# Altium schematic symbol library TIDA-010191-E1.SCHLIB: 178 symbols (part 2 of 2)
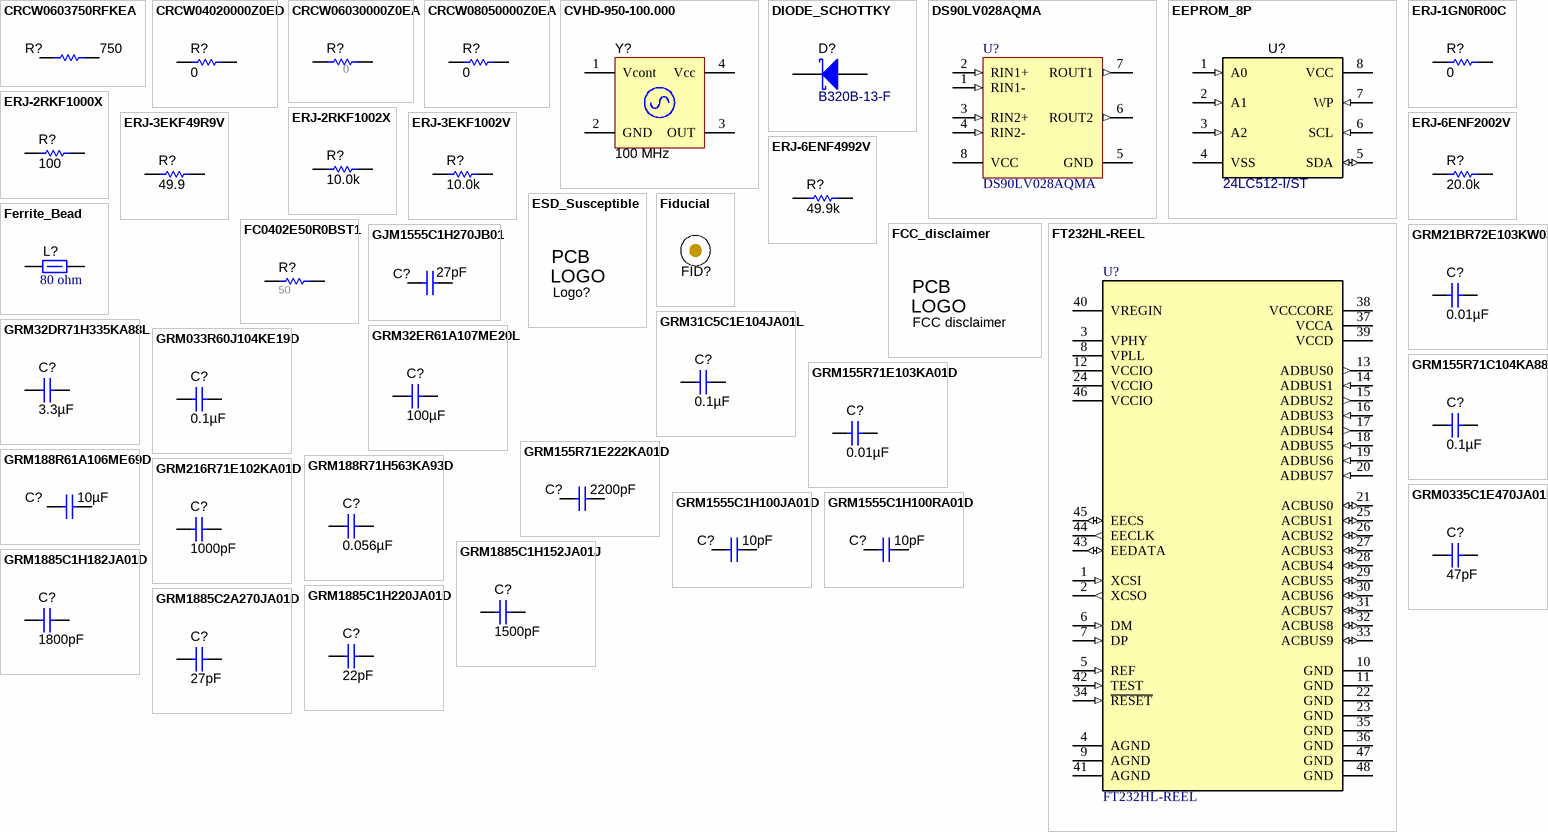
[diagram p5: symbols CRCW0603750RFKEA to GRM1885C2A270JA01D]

## GRM31C5C1E104JA01L
designator C?  ValueDisplayed: 0.1µF  (hidden comment: GRM31C5C1E104JA01L)
CAP, CERM, 0.1 µF, 25 V,+/- 5%, C0G/NP0, 1206; Manufacturer: MuRata; Polarized: N; CompType: Capacitor; Value: 0.1uF; U/M: EA; Cap_F: 0.0000001; Tolerance_%: 5; VDC_V: 25; Value2: 25V; TaMin_C: -55; TaMax_C: 125; Cap_Case: 1206; SizeArea_mm2: 5.12; SizeAreaWB_mm2: 10.92; SizeX_mm: 3.2; SizeY_mm: 1.6; SizeZ_mm: 1.8; AEC Category: Q200
signal-integrity model Cap
simulation model Cap
footprint 1206_180
footprint 1206_180M
footprint 1206_180L
pins: 1, 2

## GRM32DR71H335KA88L
designator C?  ValueDisplayed: 3.3µF  (hidden comment: GRM32DR71H335KA88L)
CAP, CERM, 3.3 µF, 50 V,+/- 10%, X7R, 1210; Manufacturer: MuRata; Polarized: N; CompType: Capacitor; Value: 3.3uF; U/M: EA; Cap_F: 0.0000033; Tolerance_%: 10; ESR_ohm: 0.003; Value1: 0.003 ohm; VDC_V: 50; Value2: 50V; TaMin_C: -55; TaMax_C: 125; Cap_Case: 1210; SizeArea_mm2: 8; SizeAreaWB_mm2: 14.7; SizeX_mm: 3.2; SizeY_mm: 2.5; SizeZ_mm: 2.2; AEC Category: Q200; Green_Lifecycle: Active; Green_REACh: Passed
signal-integrity model Cap
simulation model Cap
footprint 1210_220
footprint 1210_220M
footprint 1210_220L
pins: 1, 2

## GRM32ER61A107ME20L
designator C?  ValueDisplayed: 100µF  (hidden comment: GRM32ER61A107ME20L)
CAP, CERM, 100 µF, 10 V, +/- 20%, X5R, 1210; Manufacturer: MuRata; Polarized: N; CompType: Capacitor; Value: 100uF; U/M: EA; Cap_F: 0.0001; Tolerance_%: 20; Value1: Unknown; VDC_V: 10; Value2: 10V; TaMin_C: -55; TaMax_C: 85; Cap_Case: 1210; SizeArea_mm2: 8; SizeAreaWB_mm2: 14.7; SizeX_mm: 3.2; SizeY_mm: 2.5; SizeZ_mm: 2.7; AEC Category: Q200
signal-integrity model Cap
simulation model Cap
footprint 1210_270
footprint 1210_270M
footprint 1210_270L
pins: 1, 2

## GRM033R60J104KE19D
designator C?  ValueDisplayed: 0.1µF  (hidden comment: GRM033R60J104KE19D)
CAP, CERM, 0.1 µF, 6.3 V, +/- 10%, X5R, 0201; Manufacturer: MuRata; Polarized: N; CompType: Capacitor; Value: 0.1uF; U/M: EA; Cap_F: 0.0000001; Tolerance_%: 10; Value1: Unknown; VDC_V: 6.3; Value2: 6.3V; TaMin_C: -55; TaMax_C: 85; Cap_Case: 0201; SizeArea_mm2: 0.18; SizeAreaWB_mm2: 2.08; SizeX_mm: 0.6; SizeY_mm: 0.3; SizeZ_mm: 0.33; AEC Category: Q200
signal-integrity model Cap
simulation model Cap
footprint 0201_033
footprint 0201_033M
footprint 0201_033L
pins: 1, 2

## GRM155R71C104KA88D
designator C?  ValueDisplayed: 0.1µF  (hidden comment: GRM155R71C104KA88D)
CAP, CERM, 0.1 µF, 16 V, +/- 10%, X7R, 0402; Manufacturer: MuRata; Polarized: N; CompType: Capacitor; Value: 0.1uF; U/M: EA; Cap_F: 0.0000001; Tolerance_%: 10; Value1: Unknown; VDC_V: 16; Value2: 16V; TaMin_C: -55; TaMax_C: 125; Cap_Case: 0402; SizeArea_mm2: 0.5; SizeAreaWB_mm2: 3; SizeX_mm: 1; SizeZ_mm: 0.6; AEC Category: Q200
signal-integrity model Cap
simulation model Cap
footprint 0402
footprint 0402M
footprint 0402L
footprint 0402S
pins: 1, 2

## GRM155R71E103KA01D
designator C?  ValueDisplayed: 0.01µF  (hidden comment: GRM155R71E103KA01D)
CAP, CERM, 0.01 µF, 25 V, +/- 10%, X7R, 0402; Manufacturer: MuRata; Polarized: N; CompType: Capacitor; Value: 0.01uF; U/M: EA; Cap_F: 0.00000001; Tolerance_%: 10; Value1: Unknown; VDC_V: 25; Value2: 25V; TaMin_C: -55; TaMax_C: 125; Cap_Case: 0402; SizeArea_mm2: 0.5; SizeAreaWB_mm2: 3; SizeX_mm: 1; SizeZ_mm: 0.6; AEC Category: Q200
signal-integrity model Cap
simulation model Cap
footprint 0402
footprint 0402M
footprint 0402L
footprint 0402S
pins: 1, 2

## GRM155R71E222KA01D
designator C?  ValueDisplayed: 2200pF  (hidden comment: GRM155R71E222KA01D)
CAP, CERM, 2200 pF, 25 V, +/- 10%, X7R, 0402; Manufacturer: MuRata; Polarized: N; CompType: Capacitor; Value: 2200pF; U/M: EA; Cap_F: 0.0000000022; Tolerance_%: 10; Value1: Unknown; VDC_V: 25; Value2: 25V; TaMin_C: -55; TaMax_C: 125; Cap_Case: 0402; SizeArea_mm2: 0.5; SizeAreaWB_mm2: 3; SizeX_mm: 1; SizeZ_mm: 0.6; AEC Category: Q200
signal-integrity model Cap
simulation model Cap
footprint 0402
footprint 0402M
footprint 0402L
footprint 0402S
pins: 1, 2

## GRM188R61A106ME69D
designator C?  ValueDisplayed: 10µF  (hidden comment: GRM188R61A106ME69D)
CAP, CERM, 10 µF, 10 V, +/- 20%, X5R, 0603; Manufacturer: MuRata; Polarized: N; CompType: Capacitor; Value: 10uF; U/M: EA; Cap_F: 0.00001; Tolerance_%: 20; Value1: Unknown; VDC_V: 10; Value2: 10V; TaMin_C: -55; TaMax_C: 85; Cap_Case: 0603; SizeArea_mm2: 1.28; SizeAreaWB_mm2: 4.68; SizeX_mm: 1.6; SizeY_mm: 0.8; SizeZ_mm: 1; AEC Category: Q200
signal-integrity model Cap
simulation model Cap
footprint 0603
footprint 0603M
footprint 0603L
footprint 0603_HV
footprint 0603S
pins: 1, 2

## GRM188R71H563KA93D
designator C?  ValueDisplayed: 0.056µF  (hidden comment: GRM188R71H563KA93D)
CAP, CERM, 0.056 µF, 50 V,+/- 10%, X7R, 0603; Manufacturer: MuRata; Cap_Case: 0603; Polarized: N; TaMax_C: 125; TaMin_C: -55; Tolerance_%: 10; VDC_V: 50; Cap_F: 0.000000056; CompType: Capacitor; Value: 0.056uF; Value2: 50V; U/M: EA; AEC Category: Q200; SizeArea_mm2: 1.28; SizeAreaWB_mm2: 4.68; SizeX_mm: 1.6; SizeY_mm: 0.8; SizeZ_mm: 1; Green_Lifecycle: Active; Green_REACh: Passed
signal-integrity model Cap
simulation model Cap
footprint 0603
footprint 0603M
footprint 0603L
footprint 0603_HV
footprint 0603S
pins: 1, 2

## GRM216R71E102KA01D
designator C?  ValueDisplayed: 1000pF  (hidden comment: GRM216R71E102KA01D)
CAP, CERM, 1000 pF, 25 V,+/- 10%, X7R, 0805; Manufacturer: MuRata; Polarized: N; CompType: Capacitor; Value: 1000pF; U/M: EA; Cap_F: 0.000000001; Tolerance_%: 10; VDC_V: 25; Value2: 25V; TaMin_C: -55; TaMax_C: 125; Cap_Case: 0805; SizeArea_mm2: 2.5; SizeAreaWB_mm2: 6.75; SizeX_mm: 2; SizeY_mm: 1.25; SizeZ_mm: 1.45; AEC Category: Q200; Green_Lifecycle: Active; Green_REACh: Passed
signal-integrity model Cap
simulation model Cap
footprint 0805_HV
footprint 0805_HV1
footprint 0805
footprint 0805M
footprint 0805L
pins: 1, 2

## GRM0335C1E470JA01D
designator C?  ValueDisplayed: 47pF  (hidden comment: GRM0335C1E470JA01D)
CAP, CERM, 47 pF, 25 V, +/- 5%, C0G/NP0, 0201; Manufacturer: MuRata; Polarized: N; CompType: Capacitor; Value: 47pF; U/M: EA; Cap_F: 0.000000000047; Tolerance_%: 5; Value1: Unknown; VDC_V: 25; Value2: 25V; TaMin_C: -55; TaMax_C: 125; Cap_Case: 0201; SizeArea_mm2: 0.18; SizeAreaWB_mm2: 2.08; SizeX_mm: 0.6; SizeY_mm: 0.3; SizeZ_mm: 0.33; AEC Category: Q200
signal-integrity model Cap
simulation model Cap
footprint 0201_033
footprint 0201_033M
footprint 0201_033L
pins: 1, 2

## GRM1555C1H100JA01D
designator C?  ValueDisplayed: 10pF  (hidden comment: GRM1555C1H100JA01D)
CAP, CERM, 10 pF, 50 V, +/- 5%, C0G/NP0, 0402; Manufacturer: MuRata; Polarized: N; CompType: Capacitor; Value: 10pF; U/M: EA; Cap_F: 0.00000000001; Tolerance_%: 5; Value1: Unknown; VDC_V: 50; Value2: 50V; TaMin_C: -55; TaMax_C: 125; Cap_Case: 0402; SizeArea_mm2: 0.5; SizeAreaWB_mm2: 3; SizeX_mm: 1; SizeZ_mm: 0.6; AEC Category: Q200
signal-integrity model Cap
simulation model Cap
footprint 0402
footprint 0402M
footprint 0402L
footprint 0402S
pins: 1, 2

## GRM1555C1H100RA01D
designator C?  ValueDisplayed: 10pF  (hidden comment: GRM1555C1H100RA01D)
CAP, CERM, 10 pF, 50 V,+/- 4%, C0G/NP0, 0402; Manufacturer: MuRata; Polarized: N; CompType: Capacitor; Value: 10pF; U/M: EA; Cap_F: 0.00000000001; Tolerance_%: 4; VDC_V: 50; Value2: 50V; TaMin_C: -55; TaMax_C: 125; Cap_Case: 0402; SizeArea_mm2: 0.5; SizeAreaWB_mm2: 3; SizeX_mm: 1; SizeZ_mm: 0.6; AEC Category: Q200
signal-integrity model Cap
simulation model Cap
footprint 0402
footprint 0402M
footprint 0402L
footprint 0402S
pins: 1, 2

## GRM1885C1H152JA01J
designator C?  ValueDisplayed: 1500pF  (hidden comment: GRM1885C1H152JA01J)
CAP, CERM, 1500 pF, 50 V,+/- 5%, C0G/NP0, 0603; Manufacturer: MuRata; Cap_Case: 0603; Polarized: N; TaMax_C: 125; TaMin_C: -55; Tolerance_%: 5; VDC_V: 50; Cap_F: 0.0000000015; CompType: Capacitor; Value: 1500pF; Value2: 50V; U/M: EA; AEC Category: Q200; SizeArea_mm2: 1.28; SizeAreaWB_mm2: 4.68; SizeX_mm: 1.6; SizeY_mm: 0.8; SizeZ_mm: 1
signal-integrity model Cap
simulation model Cap
footprint 0603
footprint 0603M
footprint 0603L
footprint 0603_HV
footprint 0603S
pins: 1, 2

## GRM1885C1H182JA01D
designator C?  ValueDisplayed: 1800pF  (hidden comment: GRM1885C1H182JA01D)
CAP, CERM, 1800 pF, 50 V,+/- 5%, C0G/NP0, 0603; Manufacturer: MuRata; Cap_Case: 0603; Polarized: N; TaMax_C: 125; TaMin_C: -55; Tolerance_%: 5; VDC_V: 50; Cap_F: 0.0000000018; CompType: Capacitor; Value: 1800pF; Value2: 50V; U/M: EA; SizeArea_mm2: 1.28; SizeAreaWB_mm2: 4.68; SizeX_mm: 1.6; SizeY_mm: 0.8; SizeZ_mm: 1; AEC Category: Q200
signal-integrity model Cap
simulation model Cap
footprint 0603
footprint 0603M
footprint 0603L
footprint 0603_HV
footprint 0603S
pins: 1, 2

## GRM1885C1H220JA01D
designator C?  ValueDisplayed: 22pF  (hidden comment: GRM1885C1H220JA01D)
CAP, CERM, 22 pF, 50 V,+/- 5%, C0G/NP0, 0603; Manufacturer: MuRata; Polarized: N; CompType: Capacitor; Value: 22pF; U/M: EA; Cap_F: 0.000000000022; Tolerance_%: 5; VDC_V: 50; Value2: 50V; TaMin_C: -55; TaMax_C: 125; Cap_Case: 0603; SizeArea_mm2: 1.28; SizeAreaWB_mm2: 4.68; SizeX_mm: 1.6; SizeY_mm: 0.8; SizeZ_mm: 1; AEC Category: Q200; Green_Lifecycle: Active; Green_REACh: Passed
signal-integrity model Cap
simulation model Cap
footprint 0603
footprint 0603M
footprint 0603L
footprint 0603_HV
footprint 0603S
pins: 1, 2

## GRM1885C2A270JA01D
designator C?  ValueDisplayed: 27pF  (hidden comment: GRM1885C2A270JA01D)
CAP, CERM, 27 pF, 100 V, +/- 5%, C0G/NP0, 0603; Manufacturer: MuRata; Polarized: N; CompType: Capacitor; Value: 27pF; U/M: EA; Cap_F: 0.000000000027; Tolerance_%: 5; Value1: Unknown; VDC_V: 100; Value2: 100V; TaMin_C: -55; TaMax_C: 125; Cap_Case: 0603; SizeArea_mm2: 1.28; SizeAreaWB_mm2: 4.68; SizeX_mm: 1.6; SizeY_mm: 0.8; SizeZ_mm: 1; AEC Category: Q200
signal-integrity model Cap
simulation model Cap
footprint 0603
footprint 0603M
footprint 0603L
footprint 0603_HV
footprint 0603S
pins: 1, 2

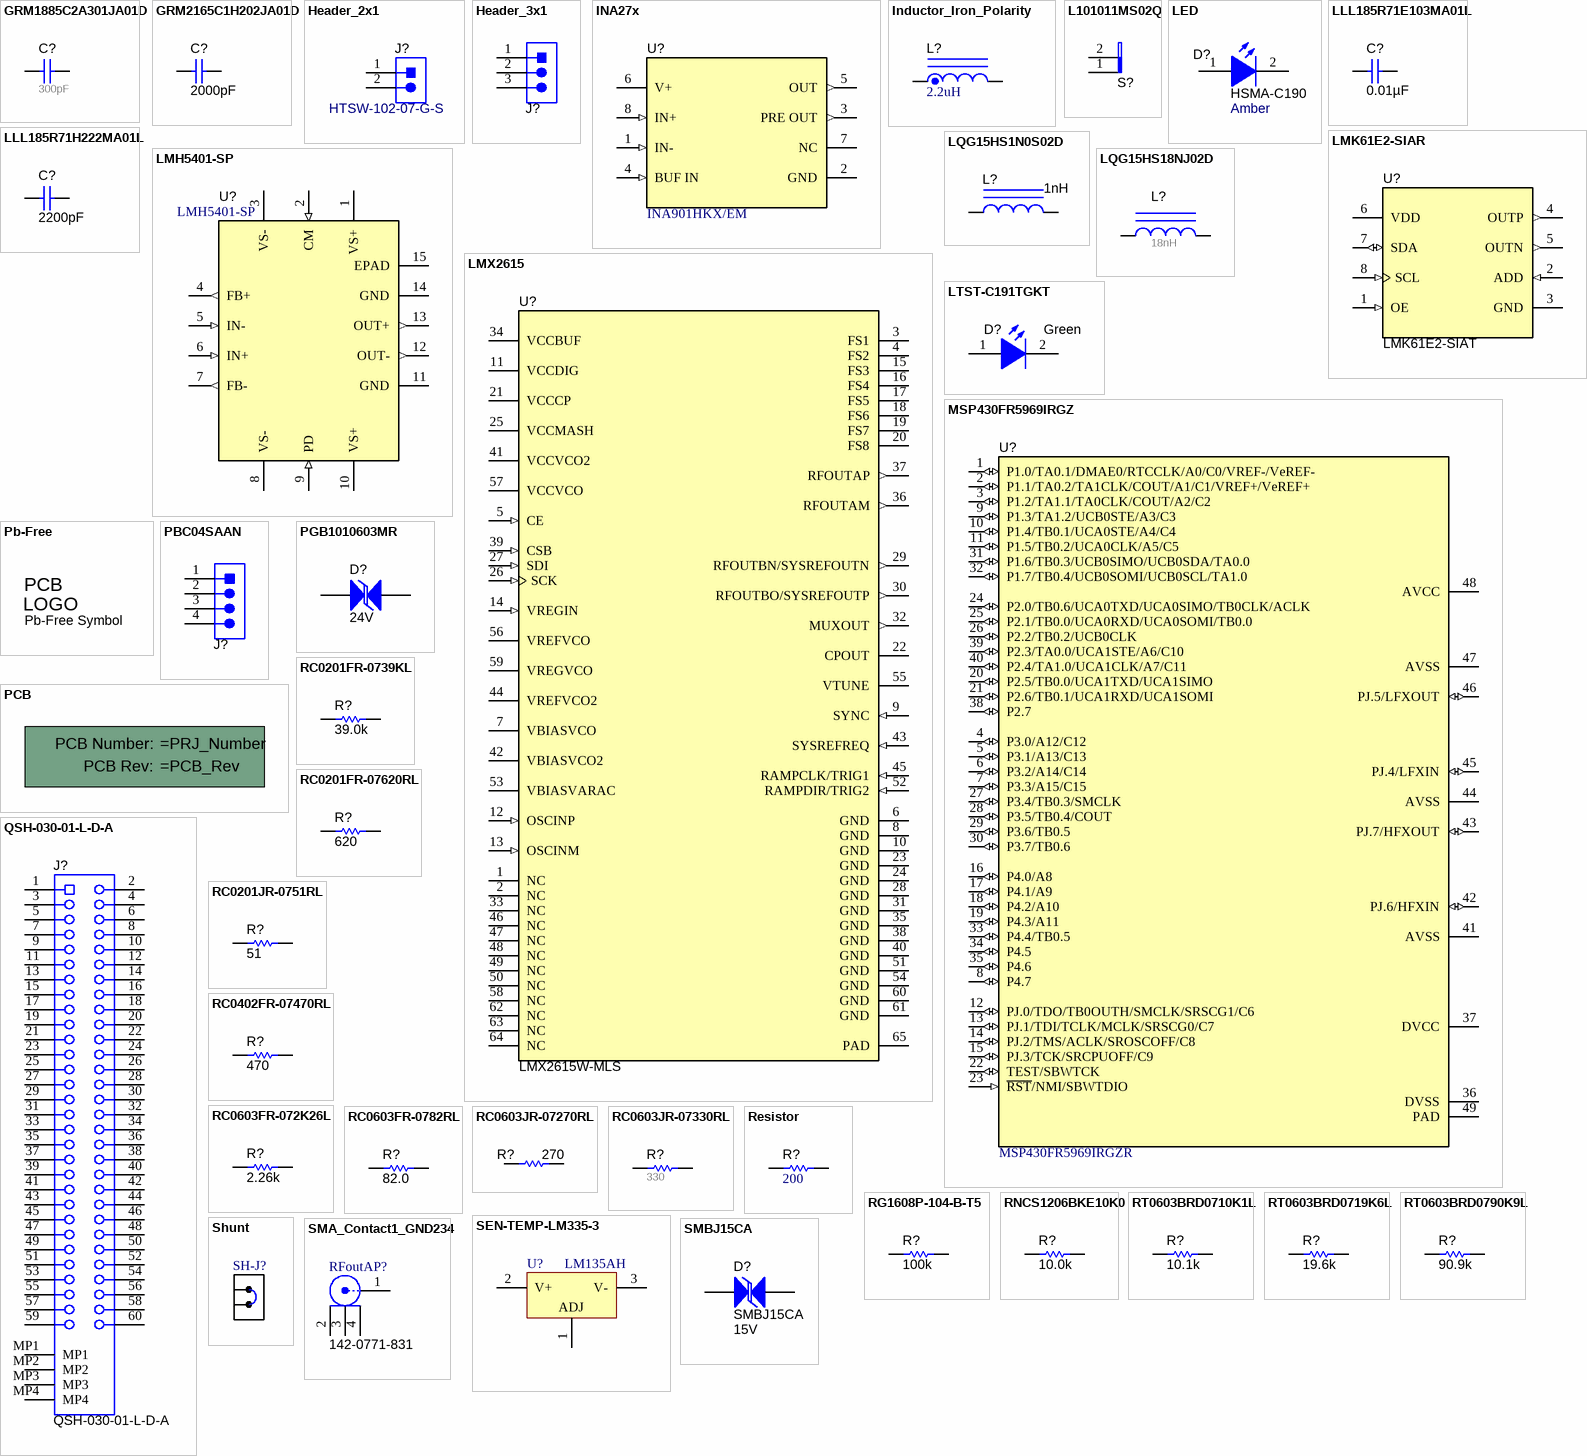
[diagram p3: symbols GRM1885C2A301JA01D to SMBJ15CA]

## GRM1885C2A301JA01D
designator C?  ValueDisplayed: 300pF  (hidden comment: GRM1885C2A301JA01D)
CAP, CERM, 300pF, 100V, +/-5%, C0G/NP0, 0603; Manufacturer: MuRata; Cap_Case: 0603; Polarized: N; TaMax_C: 125; TaMin_C: -55; Tolerance_%: 5; VDC_V: 100; Cap_F: 0.0000000003; CompType: Capacitor; Value1: Unknown; U/M: EA
signal-integrity model Cap
simulation model Cap
footprint 0603
footprint 0603M
footprint 0603L
footprint 0603_HV
footprint 0603S
pins: 1, 2

## GRM2165C1H202JA01D
designator C?  ValueDisplayed: 2000pF  (hidden comment: GRM2165C1H202JA01D)
CAP, CERM, 2000 pF, 50 V,+/- 5%, C0G/NP0, 0805; Manufacturer: MuRata; Polarized: N; CompType: Capacitor; Value: 2000pF; U/M: EA; Cap_F: 0.000000002; Tolerance_%: 5; VDC_V: 50; Value2: 50V; TaMin_C: -55; TaMax_C: 125; Cap_Case: 0805; SizeArea_mm2: 2.5; SizeAreaWB_mm2: 6.75; SizeX_mm: 2; SizeY_mm: 1.25; SizeZ_mm: 1.45; AEC Category: Q200
signal-integrity model Cap
simulation model Cap
footprint 0805_HV
footprint 0805_HV1
footprint 0805
footprint 0805M
footprint 0805L
pins: 1, 2

## Header_2x1
designator J?, comment HTSW-102-07-G-S
Header, 100mil, 2x1, Gold, TH; Manufacturer: Samtec; Green_REACh: Passed; CT: False; Green_Lifecycle: Active; CNHeader: True
footprint Samtec_HTSW-102-07-G-S (Samtec 100mil, 1x2, 230 mil above insulator)
pins: 1, 2
1 alternate drawing of the same symbol

## Header_3x1
designator J?, comment HTSW-103-07-G-S  (value not drawn)
Header, 100mil, 3x1, Gold, TH; Manufacturer: Samtec; Green_REACh: Passed; CT: False; Green_Lifecycle: Active; CNHeader: True
footprint Samtec_HTSW-103-07-G-S (Samtec 100mil, 1x3, 230 mil above insulator)
pins: 1, 2, 3
3 alternate drawings of the same symbol

## INA27x
designator U?, comment INA901HKX/EM
Voltage Output, Unidirectional Measurement Current-Shunt Monitor, HKX0008A (CFP-8); Manufacturer: Texas Instruments; SizeZ_mm: 2.8; Rating: Space; AEC Category: Q200; CompType: IC; AEC Qualified: N
footprint HKX0008A_Custom_A (CFP, 8-Leads, Body 6.475x6.485mm, Pitch 1.27mm)
footprint HKX0008A_Custom_B (CFP, 8-Leads, Body 6.73x6.74mm (max), Pitch 1.27mm, IPC Medium Density)
pins: 1 IN- (in), 2 GND (power), 3 PRE OUT (out), 4 BUF IN (in), 5 OUT (out), 6 V+ (power), 7 NC, 8 IN+ (in)

## Inductor_Iron_Polarity
designator L?, comment ValueDisplayed: 2.2uH  (hidden comment: AE611PYA222MSZ)
Inductor, Composite, 2.2 uH, 18.4 A, 0.0028 ohm, SMD; Manufacturer: Coilcraft CPS; Isat: 34A @ 30% inductance drop; Irms: 18.4A @ 20C rise; Green_Lifecycle: Not Set; SizeAreaWB_mm2: 159.6; DCR_ohm: 2.8m; Green_REACh: Incomplete; Value: 2.2uH; Imax_A: 18.4A; SizeZ_mm: 10; SizeY_mm: 11.3; SizeArea_mm2: 113; Ind_H: 2.2µH; AEC Qualified: N; AEC Category: Q200
footprint AE611PYA_1011 (Coilcraft)
pins: 1, 2

## L101011MS02Q
designator S?  (value not drawn)
SWITCH SLIDE SPST 4A PCB, TH; Manufacturer: C&K Components; Symbol Creator: a0411947; VDC_V: 125; SwitchFunction: Off-On; PositionCount: 1; CurrentRating_mA: 4000
footprint SW_ L101011MS02Q (SWITCH SLIDE sPST 4A PCB)
pins: 1, 2

## LED
designator D?, comment HSMA-C190  value Amber
LED, Amber, SMD; Manufacturer: Avago; Io_A: 20mA; Power_TotalModule: 60mW; SizeAreaWB_mm2: 4.68; Vr_V: 5V; Tjmax_C: 95°C; Value1: 0.06W; U/M: EA; Angle: 170; SizeZ_mm: 0.9; SizeX_mm: 1.6; SizeY_mm: 0.8; Ir_A: 100µA; Vf_V: 1.9V; SizeArea_mm2: 1.28; Type: AlInGaP
footprint HSMx-C190_Amber (SMD, 2-Leads, Body 1.6x0.8mm)
pins: 1 A, 2 K

## LLL185R71E103MA01L
designator C?  ValueDisplayed: 0.01µF  (hidden comment: LLL185R71E103MA01L)
CAP, CERM, 0.01 µF, 25 V, +/- 20%, X7R, 0306; Manufacturer: MuRata; Polarized: N; CompType: Capacitor; Value: 0.01uF; U/M: EA; Cap_F: 0.00000001; Tolerance_%: 20; Value1: Unknown; VDC_V: 25; Value2: 25V; TaMin_C: -55; TaMax_C: 125; Cap_Case: 0306; SizeArea_mm2: 1.28; SizeAreaWB_mm2: 4.68; SizeX_mm: 0.8; SizeY_mm: 1.6; SizeZ_mm: 0.6; AEC Category: Q200
signal-integrity model Cap
simulation model Cap
footprint 0306
pins: 1, 2

## LLL185R71H222MA01L
designator C?  ValueDisplayed: 2200pF  (hidden comment: LLL185R71H222MA01L)
CAP, CERM, 2200 pF, 50 V, +/- 20%, X7R, 0306; Manufacturer: MuRata; Polarized: N; CompType: Capacitor; Value: 2200pF; U/M: EA; Cap_F: 0.0000000022; Tolerance_%: 20; Value1: Unknown; VDC_V: 50; Value2: 50V; TaMin_C: -55; TaMax_C: 125; Cap_Case: 0306; SizeArea_mm2: 1.28; SizeAreaWB_mm2: 4.68; SizeX_mm: 0.8; SizeY_mm: 1.6; SizeZ_mm: 0.6; AEC Category: Q200
signal-integrity model Cap
simulation model Cap
footprint 0306
pins: 1, 2

## LMH5401-SP
designator U?
LMH5401-SP, FFJ0014A (LCCC-14); Manufacturer: Texas Instruments; SizeZ_mm: 2.26; SizeX_mm: 6.0; SizeY_mm: 5.5; SizeArea_mm2: 33.0; CompType: IC; U/M: EA; SizeAreaWB_mm2: 60.0
footprint FFJ0014A (LCCC, 14-Leads, Body 6x5.5mm, Pitch 1.27mm)
pins: 1 VS+ (power) "Power supply pins, Positive Rail", 2 CM (in) "Output common-mode voltage control input pin", 3 VS- (power) "Power supply pins, Negative Rail", 4 FB+ (out) "No internal connection", 5 IN- (in) "Inverting input pin", 6 IN+ (in) "Noninverting input pin", 7 FB- (out) "No internal connection", 8 VS- (power), 9 PD (in) "Power down. High (>GND+1.2V) = low power (sleep) mode. Low (<GND +0.9V)= active.", 10 VS+ (power) "Power supply pins, Positive Rail", 11 GND (power) "Ground. This ground does not impact the signal path. This ground sets the lower logic level for the PD pin.", 12 OUT- (out) "Inverting output pin", 13 OUT+ (out) "Noninverting output pin", 14 GND (power) "Ground. This ground does not impact the signal path. This ground sets the lower logic level for the PD pin.", 15 EPAD (power) "Ground. This ground does not impact the signal path. This ground sets the lower logic level for the PD pin."

## LMK61E2-SIAR
designator U?, comment LMK61E2-SIAT
Ultra-Low Jitter Programmable Oscillator with Internal EEPROM, SIA0008B; Manufacturer: Texas Instruments; SymbolCreator: Altium; CompType: IC; U/M: EA
footprint SIA0008B
pins: 1 OE (in), 2 ADD (in), 3 GND (power), 4 OUTP (out), 5 OUTN (out), 6 VDD (power), 7 SDA (io), 8 SCL (in)

## LMX2615
designator U?, comment LMX2615W-MLS
Space Grade 40 MHz to 15 GHz Wideband Synthesizer with Phase Synchronization and JESD204B Support, HBD0064A (CFP-64); Manufacturer: Texas Instruments; CompType: IC; SizeZ_mm: 2.31; AEC Category: Q200; AEC Qualified: N
footprint HBD0064A_Custom_A (CFP, 64-Leads, Body 10.9x10.9mm, Pitch 0.5 mm)
pins: 1 NC, 2 NC, 3 FS1, 4 FS2, 5 CE (in), 6 GND (power), 7 VBIASVCO (power), 8 GND (power), 9 SYNC (in), 10 GND (power), 11 VCCDIG (power), 12 OSCINP (in), 13 OSCINM (in), 14 VREGIN (in), 15 FS3, 16 FS4, 17 FS5, 18 FS6, 19 FS7, 20 FS8, 21 VCCCP (power), 22 CPOUT, 23 GND (power), 24 GND (power), 25 VCCMASH (power), 26 SCK (in), 27 SDI (in), 28 GND (power), 29 RFOUTBN/SYSREFOUTN (out), 30 RFOUTBO/SYSREFOUTP (out), 31 GND (power), 32 MUXOUT (out), 33 NC, 34 VCCBUF (power), 35 GND (power), 36 RFOUTAM (out), 37 RFOUTAP (out), 38 GND (power), 39 CSB (in), 40 GND (power), 41 VCCVCO2 (power), 42 VBIASVCO2 (power), 43 SYSREFREQ (in), 44 VREFVCO2 (power), 45 RAMPCLK/TRIG1 (in), 46 NC, 47 NC, 48 NC, 49 NC, 50 NC, 51 GND (power), 52 RAMPDIR/TRIG2 (in), 53 VBIASVARAC (power), 54 GND (power), 55 VTUNE, 56 VREFVCO, 57 VCCVCO (power), 58 NC, 59 VREGVCO (power), 60 GND (power), 61 GND (power), 62 NC, 63 NC, 64 NC, 65 PAD (power)

## LQG15HS1N0S02D
designator L?  ValueDisplayed: 1nH  (hidden comment: LQG15HS1N0S02D)
Inductor, Multilayer, Air Core, 1 nH, 0.3 A, 0.07 ohm, SMD; Manufacturer: MuRata; Value: 1nH; Ind_H: 1.0E-9; Imax_A: 0.3; Irms: 0.3A @ C rise; Isat: 0.3A @ % inductance drop; DCR_ohm: 0.07; Value2: 0.3A; SizeAreaWB_mm2: 3; SizeArea_mm2: 0.5; SizeX_mm: 1; SizeZ_mm: 0.55; AEC Category: Q200; Green_Lifecycle: Active; Green_REACh: Passed
signal-integrity model Inductor
simulation model Inductor
footprint IND_LQG15H
pins: 1, 2

## LQG15HS18NJ02D
designator L?  ValueDisplayed: 18nH  (hidden comment: LQG15HS18NJ02D)
Inductor, Multilayer, Air Core, 18 nH, 0.3 A, 0.36 ohm, SMD; Manufacturer: MuRata; Value: 18nH; Ind_H: 18.0E-9; Imax_A: 0.3; Irms: 0.3A @ C rise; Isat: 0.3A @ % inductance drop; DCR_ohm: 0.36; Value2: 0.3A; AEC Category: Q200
signal-integrity model Inductor
simulation model Inductor
footprint IND_LQG15H
pins: 1, 2

## LTST-C191TGKT
designator D?  value Green  (hidden comment: LTST-C191TGKT)
LED, Green, SMD; Manufacturer: Lite-On; Type: InGaN; Vf_V: 3.2; Value2: 3.2V; Io_A: 0.02; Value1: W; U/M: EA
signal-integrity model Diode
footprint LTST-C191_Green
pins: 1 A, 2 K

## MSP430FR5969IRGZ
designator U?, comment MSP430FR5969IRGZR
MSP430FR5969 16 MHz Ultra-Low-Power Microcontroller featuring 64 KB FRAM, 2 KB SRAM, 40 IO, RGZ0048B (VQFN-48); Manufacturer: Texas Instruments; Alternate PartNumber: MSP430FR5969IRGZT; SizeX_mm: 7; CompType: IC; SizeZ_mm: 1; SizeArea_mm2: 49; SizeAreaWB_mm2: 81; U/M: EA; Green_Lifecycle: Active; Green_REACh: Passed
footprint RGZ0048B (QFN, 48-Leads, Body 7x7mm, Pitch 0.5mm, Thermal Pad 5.15x5.15mm, TI Recommended)
footprint RGZ0048B_NV (QFN, 48-Leads, Body 7x7mm, Pitch 0.5mm, Thermal Pad 5.15x5.15mm, TI Recommended)
pins: 1 P1.0/TA0.1/DMAE0/RTCCLK/A0/C0/VREF-/VeREF- (io), 2 P1.1/TA0.2/TA1CLK/COUT/A1/C1/VREF+/VeREF+ (io), 3 P1.2/TA1.1/TA0CLK/COUT/A2/C2 (io), 4 P3.0/A12/C12 (io), 5 P3.1/A13/C13 (io), 6 P3.2/A14/C14 (io), 7 P3.3/A15/C15 (io), 8 P4.7 (io), 9 P1.3/TA1.2/UCB0STE/A3/C3 (io), 10 P1.4/TB0.1/UCA0STE/A4/C4 (io), 11 P1.5/TB0.2/UCA0CLK/A5/C5 (io), 12 PJ.0/TDO/TB0OUTH/SMCLK/SRSCG1/C6 (io), 13 PJ.1/TDI/TCLK/MCLK/SRSCG0/C7 (io), 14 PJ.2/TMS/ACLK/SROSCOFF/C8 (io), 15 PJ.3/TCK/SRCPUOFF/C9 (io), 16 P4.0/A8 (io), 17 P4.1/A9 (io), 18 P4.2/A10 (io), 19 P4.3/A11 (io), 20 P2.5/TB0.0/UCA1TXD/UCA1SIMO (io), 21 P2.6/TB0.1/UCA1RXD/UCA1SOMI (io), 22 TEST/SBWTCK (io), 23 ~{RST}/NMI/SBWTDIO (in), 24 P2.0/TB0.6/UCA0TXD/UCA0SIMO/TB0CLK/ACLK (io), 25 P2.1/TB0.0/UCA0RXD/UCA0SOMI/TB0.0 (io), 26 P2.2/TB0.2/UCB0CLK (io), 27 P3.4/TB0.3/SMCLK (io), 28 P3.5/TB0.4/COUT (io), 29 P3.6/TB0.5 (io), 30 P3.7/TB0.6 (io), 31 P1.6/TB0.3/UCB0SIMO/UCB0SDA/TA0.0 (io), 32 P1.7/TB0.4/UCB0SOMI/UCB0SCL/TA1.0 (io), 33 P4.4/TB0.5 (io), 34 P4.5 (io), 35 P4.6 (io), 36 DVSS (power), 37 DVCC (power), 38 P2.7 (io), 39 P2.3/TA0.0/UCA1STE/A6/C10 (io), 40 P2.4/TA1.0/UCA1CLK/A7/C11 (io), 41 AVSS (power), 42 PJ.6/HFXIN (io), 43 PJ.7/HFXOUT (io), 44 AVSS (power), 45 PJ.4/LFXIN (io), 46 PJ.5/LFXOUT (io), 47 AVSS (power), 48 AVCC (power), 49 PAD

## Pb-Free
designator Logo?, comment Pb-Free Symbol  (no BOM)
SymbolCreator: a0412235
footprint Pb-Free_Overlay_Medium
footprint Pb-Free_Overlay_Small

## PBC04SAAN
designator J?, comment PRPC004SAAN-RC  (value not drawn)
Header, 2.54 mm, 4x1, Gold, TH; Manufacturer: Sullins Connector Solutions; SymbolCreator: a0412235; Pitch_mm: 2.54; Gender: Male; Shrouded: N; Row_Count: 1; Current_A: 3; Voltage_V: 1800; Cert_UL: Y; Green_Lifecycle: Not Set; Green_REACh: Incomplete
footprint Sullins_xxC04SAAN
pins: 1, 2, 3, 4

## PCB
designator !PCB?, comment Printed Circuit Board  (value not drawn)  (mechanical)
Manufacturer: Any; SymbolCreator: a0412235; CompType: PCB
1 alternate drawing of the same symbol

## PGB1010603MR
designator D?  value 24V  (hidden comment: PGB1010603MR)
PulseGuard ESD Suppressor, 24VDC, SMT; Manufacturer: Littelfuse
footprint PGB1_0603
pins: 1, 2

## QSH-030-01-L-D-A
designator J?
Receptacle, 0.5 mm, 30x2, Gold, TH; Manufacturer: Samtec; SymbolCreator: Altium; Pitch_mm: 0.5; Gender: Female; Shrouded: N; Row_Count: 2; RowSpacing_mm: 5.73
footprint Samtec_QSH-030-01-X-D-A
pins: 1, 2, 3, 4, 5, 6, 7, 8, 9, 10, 11, 12, 13, 14, 15, 16, 17, 18, 19, 20, 21, 22, 23, 24, 25, 26, 27, 28, 29, 30, 31, 32, 33, 34, 35, 36, 37, 38, 39, 40, 41, 42, 43, 44, 45, 46, 47, 48, 49, 50, 51, 52, 53, 54, 55, 56, 57, 58, 59, 60, MP1, MP2, MP3, MP4

## RC0201FR-0739KL
designator R?  ValueDisplayed: 39.0k  (hidden comment: RC0201FR-0739KL)
RES, 39.0 k, 1%, 0.05 W, 0201; Manufacturer: Yageo America; CompType: Resistor; Value: 39.0k; Res_ohm: 39000; Value_Code: 39k0; Tolerance_%: 1; Power_W: 0.05; Value2: 0.05W; VDC_V: 25; TempCo: 200 ppm/C; SizeArea_mm2: 0.18; SizeX_mm: 0.6; SizeY_mm: 0.3; SizeZ_mm: 0.26; U/M: EA; AEC Category: Q200; AEC Qualified: N
signal-integrity model Resistor
simulation model Resistor
footprint 0201
footprint 0201M
footprint 0201L
footprint 0201_Silk
pins: 1, 2

## RC0201FR-07620RL
designator R?  ValueDisplayed: 620  (hidden comment: RC0201FR-07620RL)
RES, 620, 1%, 0.05 W, 0201; Manufacturer: Yageo America; CompType: Resistor; Value: 620; Value_Code: 620R; Tolerance_%: 1; Power_W: 0.05; Value2: 0.05W; VDC_V: 25; TempCo: 200 ppm/C; SizeArea_mm2: 0.18; SizeX_mm: 0.6; SizeY_mm: 0.3; SizeZ_mm: 0.26; U/M: EA; AEC Category: Q200; AEC Qualified: N
signal-integrity model Resistor
simulation model Resistor
footprint 0201
footprint 0201M
footprint 0201L
footprint 0201_Silk
pins: 1, 2

## RC0201JR-0751RL
designator R?  ValueDisplayed: 51  (hidden comment: RC0201JR-0751RL)
RES, 51, 5%, 0.05 W, 0201; Manufacturer: Yageo America; CompType: Resistor; Value: 51; Value_Code: 51R0; Tolerance_%: 5; Power_W: 0.05; Value2: 0.05W; VDC_V: 25; TempCo: 200 ppm/C; SizeArea_mm2: 0.18; SizeX_mm: 0.6; SizeY_mm: 0.3; SizeZ_mm: 0.26; EIA_Code: E24; U/M: EA; AEC Category: Q200; AEC Qualified: N
signal-integrity model Resistor
simulation model Resistor
footprint 0201
footprint 0201M
footprint 0201L
footprint 0201_Silk
pins: 1, 2

## RC0402FR-07470RL
designator R?  ValueDisplayed: 470  (hidden comment: RC0402FR-07470RL)
RES, 470, 1%, 0.063 W, 0402; Manufacturer: Yageo America; CompType: Resistor; Value: 470; Value_Code: 470R; Tolerance_%: 1; Power_W: 0.063; Value2: 0.063W; VDC_V: 50; TempCo: 100 ppm/C; SizeArea_mm2: 0.5; SizeZ_mm: 0.6; U/M: EA; AEC Category: Q200; AEC Qualified: N
signal-integrity model Resistor
simulation model Resistor
footprint 0402
footprint 0402M
footprint 0402L
footprint 0402S
pins: 1, 2

## RC0603FR-072K26L
designator R?  ValueDisplayed: 2.26k  (hidden comment: RC0603FR-072K26L)
RES, 2.26 k, 1%, 0.1 W, 0603; Manufacturer: Yageo America; CompType: Resistor; Value: 2.26k; Res_ohm: 2260; Value_Code: 2k26; Tolerance_%: 1; Power_W: 0.1; Value2: 0.1W; VDC_V: 150; TempCo: 200 ppm/C; SizeArea_mm2: 1.28; SizeX_mm: 1.6; SizeY_mm: 0.8; EIA_Code: E96; U/M: EA; AEC Category: Q200; Green_Lifecycle: Active; Green_REACh: Passed
signal-integrity model Resistor
simulation model Resistor
footprint 0603
footprint 0603M
footprint 0603L
footprint 0603_HV
footprint 0603S
pins: 1, 2

## RC0603FR-0782RL
designator R?  ValueDisplayed: 82.0  (hidden comment: RC0603FR-0782RL)
RES, 82.0, 1%, 0.1 W, 0603; Manufacturer: Yageo America; CompType: Resistor; Value: 82.0; Res_ohm: 82; Value_Code: 82R0; Tolerance_%: 1; Power_W: 0.1; Value2: 0.1W; VDC_V: 150; TempCo: 200 ppm/C; SizeArea_mm2: 1.28; SizeX_mm: 1.6; SizeY_mm: 0.8; U/M: EA; AEC Category: Q200
signal-integrity model Resistor
simulation model Resistor
footprint 0603
footprint 0603M
footprint 0603L
footprint 0603_HV
footprint 0603S
pins: 1, 2

## RC0603JR-07270RL
designator R?  ValueDisplayed: 270  (hidden comment: RC0603JR-07270RL)
RES, 270, 5%, 0.1 W, 0603; Manufacturer: Yageo America; CompType: Resistor; Tolerance_%: 5; VDC_V: 50; Power_W: 0.1; Value: 270; U/M: EA; Value_Code: 270R; Value2: 0.1W; EIA_Code: E24; TempCo: 100 ppm/C; SizeArea_mm2: 1.28; SizeX_mm: 1.6; SizeY_mm: 0.8; SizeZ_mm: 1; AEC Category: Q200
signal-integrity model Resistor
simulation model Resistor
footprint 0603
footprint 0603M
footprint 0603L
footprint 0603_HV
footprint 0603S
pins: 1, 2

## RC0603JR-07330RL
designator R?  value 330  (hidden comment: RC0603JR-07330RL)
RES, 330 ohm, 5%, 0.1W, 0603; Manufacturer: Yageo America; CompType: Resistor; Tolerance_%: 5; VDC_V: 50; Power_W: 0.1; U/M: EA; Value_Code: 330R; EIA_Code: E24
signal-integrity model Resistor
simulation model Resistor
footprint 0603
footprint 0603M
footprint 0603L
footprint 0603_HV
pins: 1, 2

## Resistor
designator R?, comment ValueDisplayed: 200  (hidden comment: CRCW0402200RFKED)
RES, 200, 1%, 0.063 W, 0402; Manufacturer: Vishay-Dale; Power_W: 63mW; TempCo: 100 ppm/C; Value_Code: 200R; U/M: EA; Value: 200; EIA_Code: E96; SizeX_mm: 1; SizeY_mm: 0.5; SizeZ_mm: 0.6; Value2: 0.063W; CompType: Resistor; VDC_V: 50V; AEC Category: Q200
footprint 0402 (0402 from SM-752 data)
footprint 0402S (Based on C0402S footprint from PADS legacy)
footprint 0402L (0402 from SM-752 data)
footprint 0402M (0402 from SM-752 data)
pins: 1, 2

## RG1608P-104-B-T5
designator R?  ValueDisplayed: 100k  (hidden comment: RG1608P-104-B-T5)
RES, 100 k, 0.1%, 0.1 W, 0603; Manufacturer: Susumu Co Ltd; CompType: Resistor; Value: 100k; Res_ohm: 100000; Tolerance_%: 0.1; Value2: 0.1W; VDC_V: 75; TempCo: 25 ppm/C; SizeArea_mm2: 1.28; SizeX_mm: 1.6; SizeY_mm: 0.8; SizeZ_mm: 1; EIA_Code: E192; U/M: EA; AEC Category: Q200; Green_Lifecycle: Active; Green_REACh: Passed
signal-integrity model Resistor
simulation model Resistor
footprint 0603
footprint 0603M
footprint 0603L
footprint 0603_HV
footprint 0603S
pins: 1, 2

## RNCS1206BKE10K0
designator R?  ValueDisplayed: 10.0k  (hidden comment: RNCS1206BKE10K0)
RES, 10.0 k, 0.1%, 0.125 W, 1206; Manufacturer: Stackpole Electronics Inc; CompType: Resistor; Value: 10.0k; Res_ohm: 10000; Value_Code: 10k0; Tolerance_%: 0.1; Power_W: 0.125; Value2: 0.125W; VDC_V: 150; TempCo: 25 ppm/C; SizeArea_mm2: 5.12; SizeX_mm: 3.2; SizeY_mm: 1.6; SizeZ_mm: 1.35; EIA_Code: E192; U/M: EA; AEC Category: Q200; AEC Qualified: N
signal-integrity model Resistor
simulation model Resistor
footprint 1206
footprint 1206M
footprint 1206L
pins: 1, 2

## RT0603BRD0710K1L
designator R?  ValueDisplayed: 10.1k  (hidden comment: RT0603BRD0710K1L)
RES, 10.1 k, 0.1%, 0.1 W, 0603; Manufacturer: Yageo America; CompType: Resistor; Value: 10.1k; Res_ohm: 10100; Value_Code: 10k1; Tolerance_%: 0.1; Value2: 0.1W; VDC_V: 75; TempCo: 25 ppm/C; SizeArea_mm2: 1.28; SizeX_mm: 1.6; SizeY_mm: 0.8; SizeZ_mm: 1; EIA_Code: E192; U/M: EA; AEC Category: Q200
signal-integrity model Resistor
simulation model Resistor
footprint 0603
footprint 0603M
footprint 0603L
footprint 0603_HV
footprint 0603S
pins: 1, 2

## RT0603BRD0719K6L
designator R?  ValueDisplayed: 19.6k  (hidden comment: RT0603BRD0719K6L)
RES, 19.6 k, 0.1%, 0.1 W, 0603; Manufacturer: Yageo America; CompType: Resistor; Value: 19.6k; Res_ohm: 19600; Value_Code: 19k6; Tolerance_%: 0.1; Value2: 0.1W; VDC_V: 75; TempCo: 25 ppm/C; SizeArea_mm2: 1.28; SizeX_mm: 1.6; SizeY_mm: 0.8; SizeZ_mm: 1; EIA_Code: E192; U/M: EA; AEC Category: Q200
signal-integrity model Resistor
simulation model Resistor
footprint 0603
footprint 0603M
footprint 0603L
footprint 0603_HV
footprint 0603S
pins: 1, 2

## RT0603BRD0790K9L
designator R?  ValueDisplayed: 90.9k  (hidden comment: RT0603BRD0790K9L)
RES, 90.9 k, 0.1%, 0.1 W, 0603; Manufacturer: Yageo America; CompType: Resistor; Value: 90.9k; Res_ohm: 90900; Value_Code: 90k9; Tolerance_%: 0.1; Value2: 0.1W; VDC_V: 75; TempCo: 25 ppm/C; SizeArea_mm2: 1.28; SizeX_mm: 1.6; SizeY_mm: 0.8; SizeZ_mm: 1; EIA_Code: E192; U/M: EA; AEC Category: Q200
signal-integrity model Resistor
simulation model Resistor
footprint 0603
footprint 0603M
footprint 0603L
footprint 0603_HV
footprint 0603S
pins: 1, 2

## SEN-TEMP-LM335-3
designator U?, comment LM135AH
Precision Temperature Sensor, 3-pin TO-46; Manufacturer: Texas Instruments; CompType: Temp Sensor IC; PackageTopMarking: NSXYTTE# LM135AH; PowerWise: N
footprint NDV0003A (Can; 3 Leads; Pin Circle Dia. 2.54 mm; Lead Dia. 0.48 mm (max))
pins: 1 ADJ, 2 V+, 3 V-

## Shunt
designator SH-J?, comment SPC02SYAN  (value not drawn)
Shunt, 100mil, Flash Gold, Black; Manufacturer: Sullins Connector Solutions; Value: 1x2
footprint SPC02SYAN (SULLINS)

## SMA_Contact1_GND234
designator RFoutAP?, comment 142-0771-831
JACK, SMA, 50 Ohm, Gold, Edge Mount; Manufacturer: Cinch Connectivity; CNHeader: FALSE; Gender: Female; Voltage_V: 170V; CT: TRUE
footprint Johnson_142-0771-831 (JACK, SMA, 50 Ohm, Gold, Edge Mount)
pins: 1, 2, 3, 4

## SMBJ15CA
designator D?  value 15V
Diode, TVS, Bi, 15 V, 24.4 Vc, SMB; Manufacturer: Fairchild Semiconductor; U/M: EA; Vr_V: 15; Value1: W; AEC Category: Q101
footprint SMB-Bi
pins: 1, 2

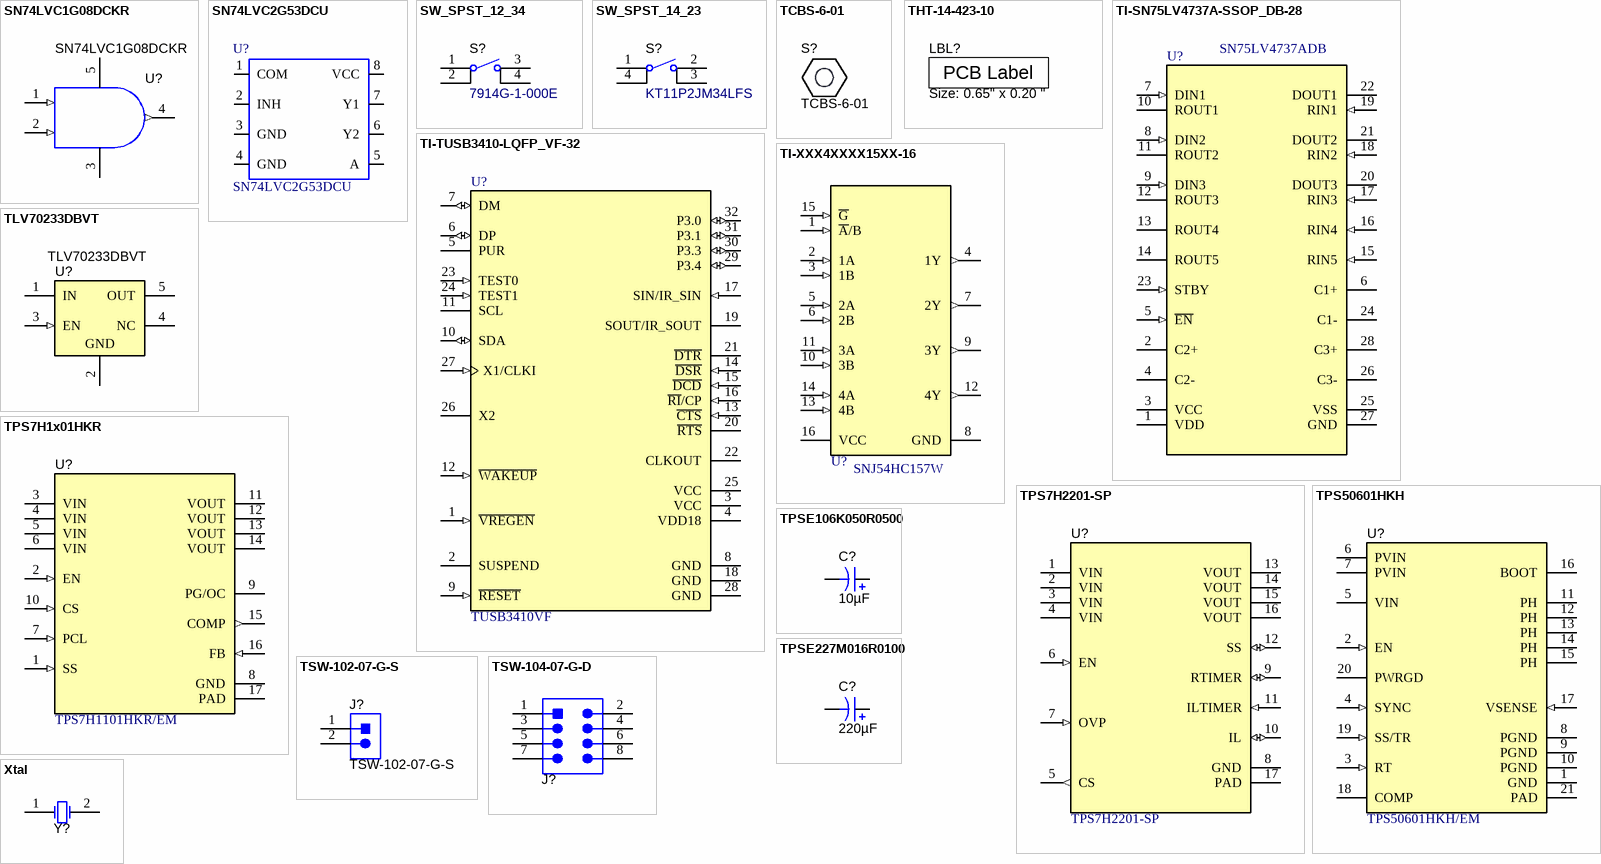
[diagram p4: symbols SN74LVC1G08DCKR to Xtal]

## SN74LVC1G08DCKR
designator U?
Single 2-Input Positive-AND Gate, DCK0005A (SOT-5); Alternate PartNumber: SN74LVC1G08DCKT; Manufacturer: Texas Instruments; CompType: IC; SizeArea_mm2: 4.2; SizeAreaWB_mm2: 9.3; SizeX_mm: 2.1; SizeY_mm: 2; SizeZ_mm: 1.1; U/M: EA
footprint DCK0005A_N
footprint DCK0005A_M
footprint DCK0005A_L
pins: 1 A (in), 2 B (in), 3 V- (power), 4 Y (out), 5 V+ (power)

## SN74LVC2G53DCU
designator U?
IC, SPDT Analog Switch; Manufacturer: TI; Alternate Manufacturer: None; Area: 36735
footprint VSSOP8
pins: 1 COM, 2 INH, 3 GND, 4 GND, 5 A, 6 Y2, 7 Y1, 8 VCC

## SW_SPST_12_34
designator S?, comment 7914G-1-000E
Switch, Tactile, SPST-NO, 0.1A, 16V, SMT; Manufacturer: Bourns; CurrentRating_mA: 100A; PositionCount: 1; SwitchFunction: Off-Mom
footprint SW_7914G-1-000E (BOURNS)
pins: 1, 2, 3, 4

## SW_SPST_14_23
designator S?, comment KT11P2JM34LFS
Switch, Tactile, SPST-NO, 1VA, 32V, SMT; Manufacturer: C&K Components; CurrentRating_mA: 1kA; PositionCount: 1; SwitchFunction: Off-Mom
footprint SW_KT11P2JM (C&K)
pins: 1, 2, 3, 4

## TCBS-6-01
designator S?
HEX STANDOFF SPACER, 9.53 mm; Manufacturer: Richco Plastics; SymbolCreator: a0412235
footprint TCBS-6-01

## THT-14-423-10
designator LBL?, comment Size: 0.65" x 0.20 "
Thermal Transfer Printable Labels, 0.650" W x 0.200" H - 10,000 per roll; Manufacturer: Brady; PartNumber: THT-14-423-10; SymbolCreator: a0412235; CompType: Label
footprint Label_650x200

## TI-SN75LV4737A-SSOP_DB-28
designator U?, comment SN75LV4737ADB
3.3-V / 5-V Multichannel RS-232 Line Driver / Receiver, 0 to 70 degC, 28-Pin SSOP (DB), Green (RoHS & no Sb/Br); ESD HBM(kV): +/-4; Single Supply: TRUE; Receivers Per Package: 5; ICC(Max)(mA): 20.7; Supply Voltage(s)(V): 3.3 or 5.0; Drivers Per Package: 3
footprint DB0028A_L (SOP, 28-Leads, Body 10.2x5.3mm, Pitch 0.65mm, IPC High Density)
footprint DB0028A_M (SOP, 28-Leads, Body 10.2x5.3mm, Pitch 0.65mm, IPC Low Density)
footprint DB0028A_N (SOP, 28-Leads, Body 10.2x5.3mm, Pitch 0.65mm, IPC Medium Density)
pins: 1 VDD (power), 2 C2+, 3 VCC (power), 4 C2-, 5 ~{EN} (in), 6 C1+, 7 DIN1 (in), 8 DIN2 (in), 9 DIN3 (in), 10 ROUT1 (hiz), 11 ROUT2 (hiz), 12 ROUT3 (hiz), 13 ROUT4 (hiz), 14 ROUT5 (hiz), 15 RIN5 (in), 16 RIN4 (in), 17 RIN3 (in), 18 RIN2 (in), 19 RIN1 (in), 20 DOUT3 (hiz), 21 DOUT2 (hiz), 22 DOUT1 (hiz), 23 STBY (in), 24 C1-, 25 VSS (power), 26 C3-, 27 GND (power), 28 C3+

## TI-TUSB3410-LQFP_VF-32
designator U?, comment TUSB3410VF
2 MIPs, RS232 / IrDA Serial-to-USB Converter, 16 KBytes, 8052, 3.3V, 0 to 70 degC, 32-Pin LQFP (VF), Green (RoHS & no Sb/Br); Manufacturer: Texas Instruments; Bulk Transfer: True; USB Speed: Full; Number of Endpoints OUT: 3; MCU Speed(Max)(MIPs): 2; Application Interface: Enhanced, UART; Supply Voltage(s)(V): 3.3; Integrated MCU Architecture: 8052; SubFamily: USB Peripheral; MCU Code Space(KBytes): 16; GPIO Pins(#): 4
footprint VF0032A_L (Thin QFP, 32-Leads, Body 7x7mm, Pitch 0.8mm, IPC High Density)
footprint VF0032A_M (Thin QFP, 32-Leads, Body 7x7mm, Pitch 0.8mm, IPC Low Density)
footprint VF0032A_N (Thin QFP, 32-Leads, Body 7x7mm, Pitch 0.8mm, IPC Medium Density)
pins: 1 ~{VREGEN} (in) "This active-low terminal is used to enable the 3.3-V to 1.8-V voltage regulator.", 2 SUSPEND (hiz) "Suspend indicator terminal (see Note 3). When this terminal is asserted high, the device is in suspend mode.", 3 VCC (power) "3.3 V", 4 VDD18 (power) "1.8-V supply. An internal voltage regulator generates this supply voltage when terminal V\R\E\G\E\N\ islow. When V\R\E\G\E\N\ is high, 1.8 V must be supplied externally.", 5 PUR (hiz) "Pull-up resistor connection (see Note 2)", 6 DP (io) "Upstream USB port differential data plus", 7 DM (io) "Upstream USB port differential data minus", 8 GND (power) "Digital ground", 9 ~{RESET} (in) "Device master reset input (see Note 4)", 10 SDA (io) "Master I2C controller: data signal (see Notes 1 and 5)", 11 SCL (hiz) "Master I2C controller: clock signal (see Note 1)", 12 ~{WAKEUP} (in) "Remote wake-up request terminal. When low, wakes up system (see Note 5)", 13 ~{CTS} (in) "UART: Clear to send (see Note 4)", 14 ~{DSR} (in) "UART: Data set ready (see Note 4)", 15 ~{DCD} (in) "UART: Data carrier detect (see Note 4)", 16 ~{RI}/CP (in) "UART: Ring indicator (see Note 4)", 17 SIN/IR_SIN (in) "UART: Serial input data / IR Serial data input (see Note 6)", 18 GND (power) "Digital ground", 19 SOUT/IR_SOUT (hiz) "UART: Serial output data / IR Serial data output (see Note 7)", 20 ~{RTS} (hiz) "UART: Request to send (see Note 1)", 21 ~{DTR} (hiz) "UART: Data terminal ready (see Note 1)", 22 CLKOUT (hiz) "Clock output (controlled by bits 2 (CLKOUTEN) and 3(CLKSLCT) in the MODECNFG register (see Section 5.5 and Note 1)", 23 TEST0 (in) "Test input (for factory test only) (see Note 5). This terminal must be tied to VCC through a 10-kO resistor.", 24 TEST1 (in) "Test input (for factory test only) (see Note 5). This terminal must be tied to VCC through a 10-kO resistor.", 25 VCC (power) "3.3 V", 26 X2 "12-MHz crystal output", 27 X1/CLKI (in) "12-MHz crystal input or clock input", 28 GND (power) "Digital ground", 29 P3.4 (io) "General-purpose I/O 4 (port 3, terminal 4) (see Notes 3, 5, and 8)", 30 P3.3 (io) "General-purpose I/O 3 (port 3, terminal 3) (see Notes 3, 5, and 8)", 31 P3.1 (io) "General-purpose I/O 1 (port 3, terminal 1) (see Notes 3, 5, and 8)", 32 P3.0 (io) "General-purpose I/O 0 (port 3, terminal 0) (see Notes 3, 5, and 8)"

## TI-XXX4XXXX15XX-16
designator U?, comment SNJ54HC157W
Quadruple 2-Line To 1-Line Data Selectors/Multiplexers, W0016A, TUBE; Manufacturer: Texas Instruments; Generic Part Number: SN54HC157; Schmitt Trigger: No; VCC(Min)(V): 2; VCC(Max)(V): 6; Rating: Military; Technology Family: HC
footprint W0016A_Custom_A (DFP, 16 Leads, Body 10.2x6.7mm, Pitch 1.27mm, Gullwing Leadform)
pins: 1 ~{A}/B (in), 2 1A (in), 3 1B (in), 4 1Y (out), 5 2A (in), 6 2B (in), 7 2Y (out), 8 GND (power), 9 3Y (out), 10 3B (in), 11 3A (in), 12 4Y (out), 13 4B (in), 14 4A (in), 15 ~{G} (in), 16 VCC (power)

## TLV70233DBVT
designator U?
Single Output LDO, 300 mA, Fixed 3.3 V Output, 2 to 5.5 V Input, with Low IQ, 5-pin SOT-23 (DBV), -40 to 125 degC, Green (RoHS & no Sb/Br); Manufacturer: Texas Instruments; Alternate PartNumber: Equivalent; Accuracy(%): 2; Fixed Output Options(V): 3.3; Iout(Max)(A): 0.3; Iq(Typ)(mA): 0.03; SubFamily: Single Channel LDO; Vdo(Typ)(mV): 220; Vin(Max)(V): 5.5
footprint DBV0005A_N (SOT23, 5-Leads, Body 2.9x1.6mm, Pitch 0.95mm, IPC Medium Density)
footprint DBV0005A_L (SOT23, 5-Leads, Body 2.9x1.6mm, Pitch 0.95mm, IPC High Density)
footprint DBV0005A_M (SOT23, 5-Leads, Body 2.9x1.6mm, Pitch 0.95mm, IPC Low Density)
pins: 1 IN (power) "Input supply voltage", 2 GND (power) "Ground", 3 EN (in) "Enable input", 4 NC "No connected", 5 OUT (power) "Regulated output voltage"

## TPS7H1x01HKR
designator U?, comment TPS7H1101HKR/EM
1.5-V to 7-V Input, 3-A, Radiation-Hardened Ultra-Low Dropout (LDO) Regulator, HKR0016A (CFP-16); Manufacturer: Texas Instruments; SizeArea_mm2: 283.09892; CompType: IC; SizeAreaWB_mm2: 359.90292; SizeY_mm: 11.26; SizeZ_mm: 2.33; U/M: EA; SizeX_mm: 25.142
footprint HKR0016A_Custom_A (16-Leads, Body 11.3x9.9mm, Pitch 1.27mm, Thermal Pad 9x6.78mm)
pins: 1 SS (in), 2 EN (in), 3 VIN (power), 4 VIN (power), 5 VIN (power), 6 VIN (power), 7 PCL (in), 8 GND (power), 9 PG/OC (oc), 10 CS (in), 11 VOUT (power), 12 VOUT (power), 13 VOUT (power), 14 VOUT (power), 15 COMP (out), 16 FB (in), 17 PAD (power)

## TPS7H2201-SP
designator U?
Radiation Hardened 7-V, 6-A Load Switch, HKR0016A (CFP-16); Manufacturer: Texas Instruments; SizeZ_mm: 2.33; SizeX_mm: 25.142; SizeY_mm: 11.26; AEC Category: Q200; AEC Qualified: N; SizeArea_mm2: 283.09892; CompType: IC; SizeAreaWB_mm2: 359.90292
footprint HKR0016A_Custom_A (16-Leads, Body 11.3x9.9mm, Pitch 1.27mm, Thermal Pad 9x6.78mm)
pins: 1 VIN (power), 2 VIN (power), 3 VIN (power), 4 VIN (power), 5 CS (out), 6 EN (in), 7 OVP (in), 8 GND (power), 9 RTIMER (io), 10 IL (io), 11 ILTIMER (in), 12 SS (io), 13 VOUT (power), 14 VOUT (power), 15 VOUT (power), 16 VOUT (power), 17 PAD (power)

## TPS50601HKH
designator U?, comment TPS50601HKH/EM
1.6-V to 6.3-V input, 6-A Synchronous Step Down Swift Converter, HKH0020A (CFP-20); Manufacturer: Texas Instruments; SizeZ_mm: 2.54; CompType: IC; U/M: EA
footprint HKH0020A_CUSTOM_A (SMD, 20-Leads, Body 12.7x7.38mm, Pitch 1.27mm)
pins: 1 GND (power), 2 EN (in), 3 RT (in), 4 SYNC (in), 5 VIN (power), 6 PVIN (power), 7 PVIN (power), 8 PGND (power), 9 PGND (power), 10 PGND (power), 11 PH (power), 12 PH (power), 13 PH (power), 14 PH (power), 15 PH (power), 16 BOOT (power), 17 VSENSE (in), 18 COMP, 19 SS/TR (in), 20 PWRGD (oc), 21 PAD

## TPSE106K050R0500
designator C?  ValueDisplayed: 10µF  (hidden comment: TPSE106K050R0500)
CAP, TA, 10 µF, 50 V, +/- 10%, 0.5 ohm, SMD; Manufacturer: AVX; Polarized: Y; CompType: Capacitor; Value: 10uF; U/M: EA; Cap_F: 0.00001; Tolerance_%: 10; Value1: 0.5 ohm; VDC_V: 50; Value2: 50V; ESR_ohm: 0.5; IRMS_A: 0.517; TaMin_C: -55; TaMax_C: 125; Cap_Case: E; SizeAreaWB_mm2: 58.59; SizeArea_mm2: 31.39; SizeX_mm: 7.3; SizeY_mm: 4.3; AEC Category: Q200
signal-integrity model Cap
simulation model Cap
footprint 7343-43
pins: 1 +, 2 -

## TPSE227M016R0100
designator C?  ValueDisplayed: 220µF  (hidden comment: TPSE227M016R0100)
CAP, TA, 220 µF, 16 V, +/- 20%, 0.1 ohm, SMD; Manufacturer: AVX; Polarized: Y; CompType: Capacitor; Value: 220uF; U/M: EA; Cap_F: 0.00022; Tolerance_%: 20; Value1: 0.1 ohm; VDC_V: 16; Value2: 16V; ESR_ohm: 0.1; IRMS_A: 1.156; TaMin_C: -55; TaMax_C: 125; Cap_Case: E; SizeAreaWB_mm2: 58.59; SizeArea_mm2: 31.39; SizeX_mm: 7.3; SizeY_mm: 4.3; AEC Category: Q200
signal-integrity model Cap
simulation model Cap
footprint 7343-43
pins: 1 +, 2 -

## TSW-102-07-G-S
designator J?
Header, 100mil, 2x1, Gold, TH; Manufacturer: Samtec; SymbolCreator: a0412235; Pitch_mm: 2.54; Gender: Male; Shrouded: N; Row_Count: 1; Current_A: 6.3; Voltage_V: 550; Cert_CSA: Y
footprint TSW-102-07-G-S
footprint TSW-102-07-X-S
pins: 1, 2
1 alternate drawing of the same symbol

## TSW-104-07-G-D
designator J?  (value not drawn)
Header, 100mil, 4x2, Gold, TH; Manufacturer: Samtec; SymbolCreator: a0411947; Pitch_mm: 2.54; Gender: Male; Shrouded: N; Row_Count: 2; Current_A: 6.3; Voltage_V: 550; Cert_CSA: Y
footprint TSW-104-07-G-D
pins: 1, 2, 3, 4, 5, 6, 7, 8

## Xtal
designator Y?, comment MS3V-T1R 32.768KHZ +/-20PPM 12.5PF  (value not drawn)
Crystal, 32.768 kHz, 12.5pF, SMD; Manufacturer: Micro Crystal AG; TaMin_C: -40°C; U/M: EA; TaMax_C: 85°C
footprint XTAL_MS3V-T1R (Micro Crystal Switzerland recommended land pattern)
pins: 1 OSC1, 2 OSC2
